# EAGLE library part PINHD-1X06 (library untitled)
PIN HEADER
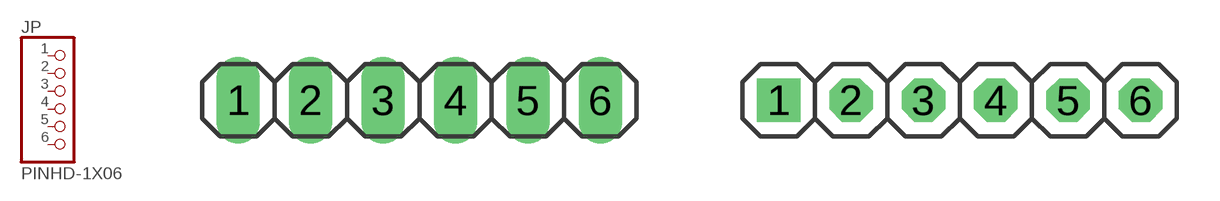
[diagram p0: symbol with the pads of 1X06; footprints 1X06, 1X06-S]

Designator prefix JP

## PINHD-1X06_2.54  [1X06]
1  1  pas
2  2  pas
3  3  pas
4  4  pas
5  5  pas
6  6  pas

## PINHD-1X06_2.54-S  [1X06-S]
Pads as for 1X06

## PINHD-1X06_2.54-90°  [1X06/90]
Pads as for 1X06

## PINHD-1X06_2.54-90°-S  [1X06/90-S]
Pads as for 1X06

## PINHD-1X06_2.00  [1X06M]
Pads as for 1X06

## PINHD-1X06_2.54-SMD  [1X06SMD]
Pads as for 1X06

## PINHD-1X06_2.54-SMD-90°  [1X06SMD/90]
Pads as for 1X06

## Footprint 1X06 (pad centres in mm)
PIN HEADER - 2.54
drill 1.016 long: 1 -6.35,0; 2 -3.81,0; 3 -1.27,0; 4 1.27,0; 5 3.81,0; 6 6.35,0

## Footprint 1X06-S (pad centres in mm)
PIN HEADER - 2.54
drill 1.016 square: 1 -6.35,0
drill 1.016 octagon: 2 -3.81,0; 3 -1.27,0; 4 1.27,0; 5 3.81,0; 6 6.35,0

## Footprint 1X06/90 (pad centres in mm)
PIN HEADER - 2.54 90°
drill 1.016 long: 1 -6.35,-3.81; 2 -3.81,-3.81; 3 -1.27,-3.81; 4 1.27,-3.81; 5 3.81,-3.81; 6 6.35,-3.81

## Footprint 1X06/90-S (pad centres in mm)
PIN HEADER - 2.54 90°
drill 1.016 square: 1 -6.35,-3.81
drill 1.016 octagon: 2 -3.81,-3.81; 3 -1.27,-3.81; 4 1.27,-3.81; 5 3.81,-3.81; 6 6.35,-3.81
